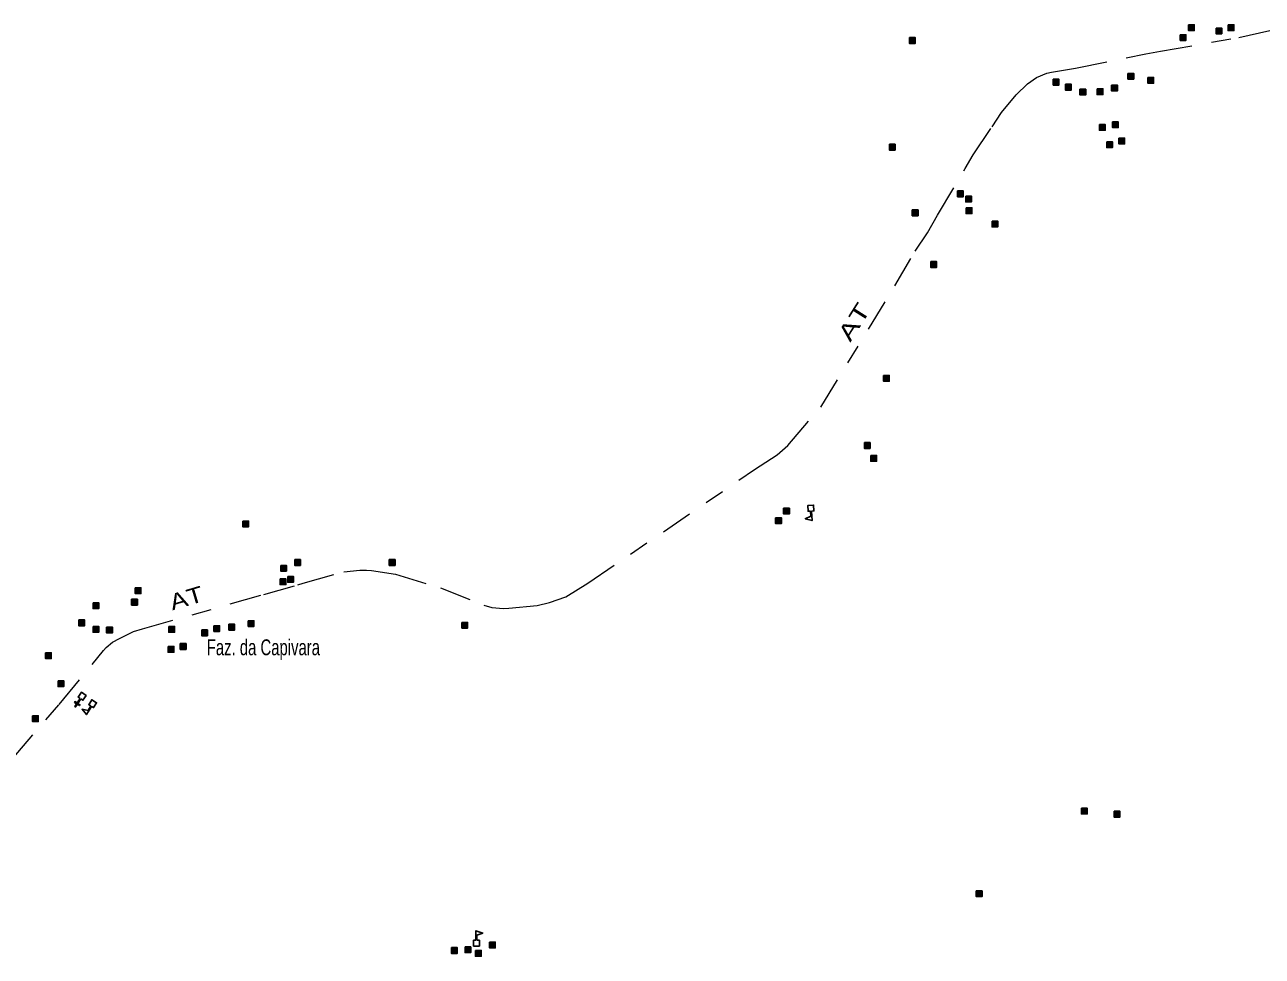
# Model space of a CAD drawing. Extents: x 220.8 to 246.7, y 7287.6 to 7315.8.
# Drawn here: x 227.09 to 233.32, y 7302.02 to 7306.71 of the extents above; entities that cross this region are included whole.
import ezdxf
from ezdxf.enums import TextEntityAlignment as Align

# ---------------------------------------------------------------- set-up
doc = ezdxf.new("R2010")
doc.units = 0
doc.header["$LTSCALE"] = 0.032
doc.linetypes.add('DOT_DASHED', pattern=[7.7, 5, -1.2, 0.3, -1.2])
for name, color, linetype, lineweight in [('2', 7, 'Continuous', 25), ('4', 7, 'Continuous', 25), ('56', 7, 'DOT_DASHED', 13), ('6', 7, 'Continuous', 25)]:
    doc.layers.add(name, color=color, linetype=linetype, lineweight=lineweight)
doc.layers.add('61', color=7, linetype='Continuous')

msp = doc.modelspace()

# ---------------------------------------------------------------- hatches: boundary and pattern name
at = {"layer": '2'}
for points in [[(232.9457, 7306.708), (232.9747, 7306.708), (232.9747, 7306.679), (232.9457, 7306.679)], [(233.0842, 7306.6913), (233.1132, 7306.6913), (233.1132, 7306.6623), (233.0842, 7306.6623)], [(233.1451, 7306.708), (233.1741, 7306.708), (233.1741, 7306.679), (233.1451, 7306.679)], [(231.5403, 7306.6434), (231.5693, 7306.6434), (231.5693, 7306.6144), (231.5403, 7306.6144)], [(232.9038, 7306.6577), (232.9328, 7306.6577), (232.9328, 7306.6287), (232.9038, 7306.6287)], [(232.2644, 7306.4334), (232.2934, 7306.4334), (232.2934, 7306.4044), (232.2644, 7306.4044)], [(232.6406, 7306.463), (232.6696, 7306.463), (232.6696, 7306.434), (232.6406, 7306.434)], [(232.7409, 7306.4425), (232.7699, 7306.4425), (232.7699, 7306.4135), (232.7409, 7306.4135)], [(232.326, 7306.4083), (232.355, 7306.4083), (232.355, 7306.3793), (232.326, 7306.3793)], [(232.3989, 7306.3833), (232.4279, 7306.3833), (232.4279, 7306.3543), (232.3989, 7306.3543)], [(232.4856, 7306.3855), (232.5146, 7306.3855), (232.5146, 7306.3565), (232.4856, 7306.3565)], [(232.5585, 7306.4038), (232.5875, 7306.4038), (232.5875, 7306.3748), (232.5585, 7306.3748)], [(232.497, 7306.2054), (232.526, 7306.2054), (232.526, 7306.1764), (232.497, 7306.1764)], [(232.5631, 7306.2191), (232.5921, 7306.2191), (232.5921, 7306.1901), (232.5631, 7306.1901)], [(231.4394, 7306.1061), (231.4684, 7306.1061), (231.4684, 7306.0771), (231.4394, 7306.0771)], [(232.5335, 7306.1188), (232.5625, 7306.1188), (232.5625, 7306.0898), (232.5335, 7306.0898)], [(232.595, 7306.137), (232.624, 7306.137), (232.624, 7306.108), (232.595, 7306.108)], [(231.7825, 7305.871), (231.8115, 7305.871), (231.8115, 7305.842), (231.7825, 7305.842)], [(231.8237, 7305.845), (231.8527, 7305.845), (231.8527, 7305.816), (231.8237, 7305.816)], [(231.5547, 7305.7756), (231.5837, 7305.7756), (231.5837, 7305.7466), (231.5547, 7305.7466)], [(231.8259, 7305.7864), (231.8549, 7305.7864), (231.8549, 7305.7574), (231.8259, 7305.7574)], [(231.9561, 7305.7192), (231.9851, 7305.7192), (231.9851, 7305.6902), (231.9561, 7305.6902)], [(231.648, 7305.5152), (231.677, 7305.5152), (231.677, 7305.4862), (231.648, 7305.4862)], [(231.41, 7304.942), (231.439, 7304.942), (231.439, 7304.913), (231.41, 7304.913)], [(231.3133, 7304.6037), (231.3423, 7304.6037), (231.3423, 7304.5747), (231.3133, 7304.5747)], [(231.3456, 7304.5393), (231.3746, 7304.5393), (231.3746, 7304.5103), (231.3456, 7304.5103)], [(230.9066, 7304.2735), (230.9356, 7304.2735), (230.9356, 7304.2445), (230.9066, 7304.2445)], [(228.183, 7304.2089), (228.212, 7304.2089), (228.212, 7304.1799), (228.183, 7304.1799)], [(230.8664, 7304.2252), (230.8954, 7304.2252), (230.8954, 7304.1962), (230.8664, 7304.1962)], [(228.374, 7303.9855), (228.403, 7303.9855), (228.403, 7303.9565), (228.374, 7303.9565)], [(228.4446, 7304.0148), (228.4736, 7304.0148), (228.4736, 7303.9858), (228.4446, 7303.9858)], [(228.9208, 7304.0148), (228.9498, 7304.0148), (228.9498, 7303.9858), (228.9208, 7303.9858)], [(228.4093, 7303.9296), (228.4383, 7303.9296), (228.4383, 7303.9006), (228.4093, 7303.9006)], [(227.6415, 7303.8726), (227.6705, 7303.8726), (227.6705, 7303.8436), (227.6415, 7303.8436)], [(228.3711, 7303.9178), (228.4001, 7303.9178), (228.4001, 7303.8888), (228.3711, 7303.8888)], [(227.6235, 7303.815), (227.6525, 7303.815), (227.6525, 7303.786), (227.6235, 7303.786)], [(227.4291, 7303.797), (227.4581, 7303.797), (227.4581, 7303.768), (227.4291, 7303.768)], [(227.3571, 7303.7106), (227.3861, 7303.7106), (227.3861, 7303.6816), (227.3571, 7303.6816)], [(227.4291, 7303.6782), (227.4581, 7303.6782), (227.4581, 7303.6492), (227.4291, 7303.6492)], [(227.4975, 7303.6746), (227.5265, 7303.6746), (227.5265, 7303.6456), (227.4975, 7303.6456)], [(227.8107, 7303.6782), (227.8397, 7303.6782), (227.8397, 7303.6492), (227.8107, 7303.6492)], [(228.0375, 7303.6818), (228.0665, 7303.6818), (228.0665, 7303.6528), (228.0375, 7303.6528)], [(228.1131, 7303.689), (228.1421, 7303.689), (228.1421, 7303.66), (228.1131, 7303.66)], [(228.2103, 7303.707), (228.2393, 7303.707), (228.2393, 7303.678), (228.2103, 7303.678)], [(229.2866, 7303.6985), (229.3156, 7303.6985), (229.3156, 7303.6695), (229.2866, 7303.6695)], [(227.9763, 7303.6602), (228.0053, 7303.6602), (228.0053, 7303.6312), (227.9763, 7303.6312)], [(227.8071, 7303.5774), (227.8361, 7303.5774), (227.8361, 7303.5484), (227.8071, 7303.5484)], [(227.8683, 7303.5918), (227.8973, 7303.5918), (227.8973, 7303.5628), (227.8683, 7303.5628)], [(227.1899, 7303.5453), (227.2189, 7303.5453), (227.2189, 7303.5163), (227.1899, 7303.5163)], [(227.2527, 7303.4046), (227.2817, 7303.4046), (227.2817, 7303.3756), (227.2527, 7303.3756)], [(227.1246, 7303.2284), (227.1536, 7303.2284), (227.1536, 7303.1994), (227.1246, 7303.1994)], [(232.4063, 7302.7629), (232.4353, 7302.7629), (232.4353, 7302.7339), (232.4063, 7302.7339)], [(232.5709, 7302.7473), (232.5999, 7302.7473), (232.5999, 7302.7183), (232.5709, 7302.7183)], [(231.8769, 7302.3467), (231.9059, 7302.3467), (231.9059, 7302.3177), (231.8769, 7302.3177)], [(229.2342, 7302.0607), (229.2632, 7302.0607), (229.2632, 7302.0317), (229.2342, 7302.0317)], [(229.3025, 7302.0646), (229.3315, 7302.0646), (229.3315, 7302.0356), (229.3025, 7302.0356)], [(229.4258, 7302.0883), (229.4548, 7302.0883), (229.4548, 7302.0593), (229.4258, 7302.0593)], [(229.355, 7302.0463), (229.384, 7302.0463), (229.384, 7302.0173), (229.355, 7302.0173)]]:
    msp.add_hatch(color=256, dxfattribs=at).paths.add_polyline_path(points)

# ---------------------------------------------------------------- linework, layer by layer
for points in [[(232.9457, 7306.708), (232.9747, 7306.708), (232.9747, 7306.679), (232.9457, 7306.679)], [(233.0842, 7306.6913), (233.1132, 7306.6913), (233.1132, 7306.6623), (233.0842, 7306.6623)], [(233.1451, 7306.708), (233.1741, 7306.708), (233.1741, 7306.679), (233.1451, 7306.679)], [(231.5403, 7306.6434), (231.5693, 7306.6434), (231.5693, 7306.6144), (231.5403, 7306.6144)], [(232.9038, 7306.6577), (232.9328, 7306.6577), (232.9328, 7306.6287), (232.9038, 7306.6287)], [(232.2644, 7306.4334), (232.2934, 7306.4334), (232.2934, 7306.4044), (232.2644, 7306.4044)], [(232.6406, 7306.463), (232.6696, 7306.463), (232.6696, 7306.434), (232.6406, 7306.434)], [(232.7409, 7306.4425), (232.7699, 7306.4425), (232.7699, 7306.4135), (232.7409, 7306.4135)], [(232.326, 7306.4083), (232.355, 7306.4083), (232.355, 7306.3793), (232.326, 7306.3793)], [(232.3989, 7306.3833), (232.4279, 7306.3833), (232.4279, 7306.3543), (232.3989, 7306.3543)], [(232.4856, 7306.3855), (232.5146, 7306.3855), (232.5146, 7306.3565), (232.4856, 7306.3565)], [(232.5585, 7306.4038), (232.5875, 7306.4038), (232.5875, 7306.3748), (232.5585, 7306.3748)], [(232.497, 7306.2054), (232.526, 7306.2054), (232.526, 7306.1764), (232.497, 7306.1764)], [(232.5631, 7306.2191), (232.5921, 7306.2191), (232.5921, 7306.1901), (232.5631, 7306.1901)], [(231.4394, 7306.1061), (231.4684, 7306.1061), (231.4684, 7306.0771), (231.4394, 7306.0771)], [(232.5335, 7306.1188), (232.5625, 7306.1188), (232.5625, 7306.0898), (232.5335, 7306.0898)], [(232.595, 7306.137), (232.624, 7306.137), (232.624, 7306.108), (232.595, 7306.108)], [(231.7825, 7305.871), (231.8115, 7305.871), (231.8115, 7305.842), (231.7825, 7305.842)], [(231.8237, 7305.845), (231.8527, 7305.845), (231.8527, 7305.816), (231.8237, 7305.816)], [(231.5547, 7305.7756), (231.5837, 7305.7756), (231.5837, 7305.7466), (231.5547, 7305.7466)], [(231.8259, 7305.7864), (231.8549, 7305.7864), (231.8549, 7305.7574), (231.8259, 7305.7574)], [(231.9561, 7305.7192), (231.9851, 7305.7192), (231.9851, 7305.6902), (231.9561, 7305.6902)], [(231.648, 7305.5152), (231.677, 7305.5152), (231.677, 7305.4862), (231.648, 7305.4862)], [(231.41, 7304.942), (231.439, 7304.942), (231.439, 7304.913), (231.41, 7304.913)], [(231.3133, 7304.6037), (231.3423, 7304.6037), (231.3423, 7304.5747), (231.3133, 7304.5747)], [(231.3456, 7304.5393), (231.3746, 7304.5393), (231.3746, 7304.5103), (231.3456, 7304.5103)], [(230.9066, 7304.2735), (230.9356, 7304.2735), (230.9356, 7304.2445), (230.9066, 7304.2445)], [(228.183, 7304.2089), (228.212, 7304.2089), (228.212, 7304.1799), (228.183, 7304.1799)], [(230.8664, 7304.2252), (230.8954, 7304.2252), (230.8954, 7304.1962), (230.8664, 7304.1962)], [(228.374, 7303.9855), (228.403, 7303.9855), (228.403, 7303.9565), (228.374, 7303.9565)], [(228.4446, 7304.0148), (228.4736, 7304.0148), (228.4736, 7303.9858), (228.4446, 7303.9858)], [(228.9208, 7304.0148), (228.9498, 7304.0148), (228.9498, 7303.9858), (228.9208, 7303.9858)], [(228.4093, 7303.9296), (228.4383, 7303.9296), (228.4383, 7303.9006), (228.4093, 7303.9006)], [(227.6415, 7303.8726), (227.6705, 7303.8726), (227.6705, 7303.8436), (227.6415, 7303.8436)], [(228.3711, 7303.9178), (228.4001, 7303.9178), (228.4001, 7303.8888), (228.3711, 7303.8888)], [(227.6235, 7303.815), (227.6525, 7303.815), (227.6525, 7303.786), (227.6235, 7303.786)], [(227.4291, 7303.797), (227.4581, 7303.797), (227.4581, 7303.768), (227.4291, 7303.768)], [(227.3571, 7303.7106), (227.3861, 7303.7106), (227.3861, 7303.6816), (227.3571, 7303.6816)], [(227.4291, 7303.6782), (227.4581, 7303.6782), (227.4581, 7303.6492), (227.4291, 7303.6492)], [(227.4975, 7303.6746), (227.5265, 7303.6746), (227.5265, 7303.6456), (227.4975, 7303.6456)], [(227.8107, 7303.6782), (227.8397, 7303.6782), (227.8397, 7303.6492), (227.8107, 7303.6492)], [(228.0375, 7303.6818), (228.0665, 7303.6818), (228.0665, 7303.6528), (228.0375, 7303.6528)], [(228.1131, 7303.689), (228.1421, 7303.689), (228.1421, 7303.66), (228.1131, 7303.66)], [(228.2103, 7303.707), (228.2393, 7303.707), (228.2393, 7303.678), (228.2103, 7303.678)], [(229.2866, 7303.6985), (229.3156, 7303.6985), (229.3156, 7303.6695), (229.2866, 7303.6695)], [(227.9763, 7303.6602), (228.0053, 7303.6602), (228.0053, 7303.6312), (227.9763, 7303.6312)], [(227.8071, 7303.5774), (227.8361, 7303.5774), (227.8361, 7303.5484), (227.8071, 7303.5484)], [(227.8683, 7303.5918), (227.8973, 7303.5918), (227.8973, 7303.5628), (227.8683, 7303.5628)], [(227.1899, 7303.5453), (227.2189, 7303.5453), (227.2189, 7303.5163), (227.1899, 7303.5163)], [(227.2527, 7303.4046), (227.2817, 7303.4046), (227.2817, 7303.3756), (227.2527, 7303.3756)], [(227.1246, 7303.2284), (227.1536, 7303.2284), (227.1536, 7303.1994), (227.1246, 7303.1994)], [(232.4063, 7302.7629), (232.4353, 7302.7629), (232.4353, 7302.7339), (232.4063, 7302.7339)], [(232.5709, 7302.7473), (232.5999, 7302.7473), (232.5999, 7302.7183), (232.5709, 7302.7183)], [(231.8769, 7302.3467), (231.9059, 7302.3467), (231.9059, 7302.3177), (231.8769, 7302.3177)], [(229.2342, 7302.0607), (229.2632, 7302.0607), (229.2632, 7302.0317), (229.2342, 7302.0317)], [(229.3025, 7302.0646), (229.3315, 7302.0646), (229.3315, 7302.0356), (229.3025, 7302.0356)], [(229.4258, 7302.0883), (229.4548, 7302.0883), (229.4548, 7302.0593), (229.4258, 7302.0593)], [(229.355, 7302.0463), (229.384, 7302.0463), (229.384, 7302.0173), (229.355, 7302.0173)]]:
    msp.add_lwpolyline(points, close=True, dxfattribs=at)
at = {"layer": '4'}
for points in [[(231.0472, 7304.2591), (231.0502, 7304.2108), (231.0156, 7304.2203), (231.0439, 7304.2328), (231.0423, 7304.2588)], [(231.0423, 7304.2588), (231.0302, 7304.2581), (231.0284, 7304.287), (231.0574, 7304.2888), (231.0592, 7304.2599), (231.0472, 7304.2591)], [(227.4176, 7303.2779), (227.4073, 7303.2841), (227.4223, 7303.3089), (227.4471, 7303.2939), (227.4321, 7303.2691), (227.4218, 7303.2753)], [(227.4218, 7303.2753), (227.3968, 7303.2339), (227.3738, 7303.2614), (227.4041, 7303.2555), (227.4176, 7303.2779)], [(229.3574, 7302.0975), (229.3574, 7302.1459), (229.3913, 7302.1343), (229.3623, 7302.1236), (229.3623, 7302.0975)], [(229.3623, 7302.0975), (229.3744, 7302.0975), (229.3744, 7302.0685), (229.3454, 7302.0685), (229.3454, 7302.0975), (229.3574, 7302.0975)]]:
    msp.add_lwpolyline(points, dxfattribs=at)
at = {"layer": '56'}
msp.add_lwpolyline([(227.0214, 7303.0103), (227.2589, 7303.2858), (227.4825, 7303.5566), (227.4951, 7303.5718), (227.5266, 7303.5994), (227.5629, 7303.6181), (227.6091, 7303.6413), (227.6329, 7303.6532), (227.6777, 7303.6662), (228.2894, 7303.8391), (228.46, 7303.8877), (228.4873, 7303.8955), (228.6917, 7303.9536), (228.773, 7303.9615), (228.8067, 7303.9607), (228.8308, 7303.9602), (228.9515, 7303.9405), (229.1785, 7303.8723), (229.3976, 7303.7857), (229.437, 7303.7739), (229.4957, 7303.7686), (229.5221, 7303.7695), (229.6653, 7303.7831), (229.7282, 7303.7988), (229.8096, 7303.8277), (229.9211, 7303.8959), (230.7595, 7304.468), (230.8737, 7304.5427), (230.9275, 7304.59), (231.0941, 7304.7829), (231.4667, 7305.393), (231.5691, 7305.5675), (231.6307, 7305.6606), (231.6815, 7305.7493), (231.8205, 7305.9838), (231.8616, 7306.0529), (231.9562, 7306.1947), (232.0034, 7306.2655), (232.0781, 7306.3547), (232.1346, 7306.4111), (232.1805, 7306.4426), (232.2317, 7306.4649), (232.256, 7306.4694), (232.3773, 7306.4899), (232.7314, 7306.5612), (232.8046, 7306.5753), (233.1986, 7306.6434), (233.3657, 7306.6808)], dxfattribs=at)
at = {"layer": '6'}
for points in [[(227.368, 7303.3129), (227.3528, 7303.2905), (227.3629, 7303.2837), (227.3601, 7303.2797), (227.3501, 7303.2864), (227.3409, 7303.2728), (227.3369, 7303.2755), (227.3461, 7303.2891), (227.3361, 7303.2959), (227.3388, 7303.2999), (227.3489, 7303.2932), (227.364, 7303.3156)], [(227.364, 7303.3156), (227.354, 7303.3224), (227.3702, 7303.3464), (227.3942, 7303.3302), (227.378, 7303.3062), (227.368, 7303.3129)]]:
    msp.add_lwpolyline(points, dxfattribs=at)

# ---------------------------------------------------------------- texts
at = {"layer": '61'}
for rotation, width, p in [(57.719, 1.45, (231.2951, 7305.19)), (16.529, 1.25, (227.9105, 7303.7829))]:
    msp.add_text('AT', height=0.08, rotation=rotation, dxfattribs=dict(at, width=width)).set_placement(p, align=Align.CENTER)
at = {"layer": '61', "width": 0.7}
msp.add_text('Faz. da Capivara', height=0.08, dxfattribs=at).set_placement((228.0018, 7303.533))

doc.saveas('drawing.dxf')
